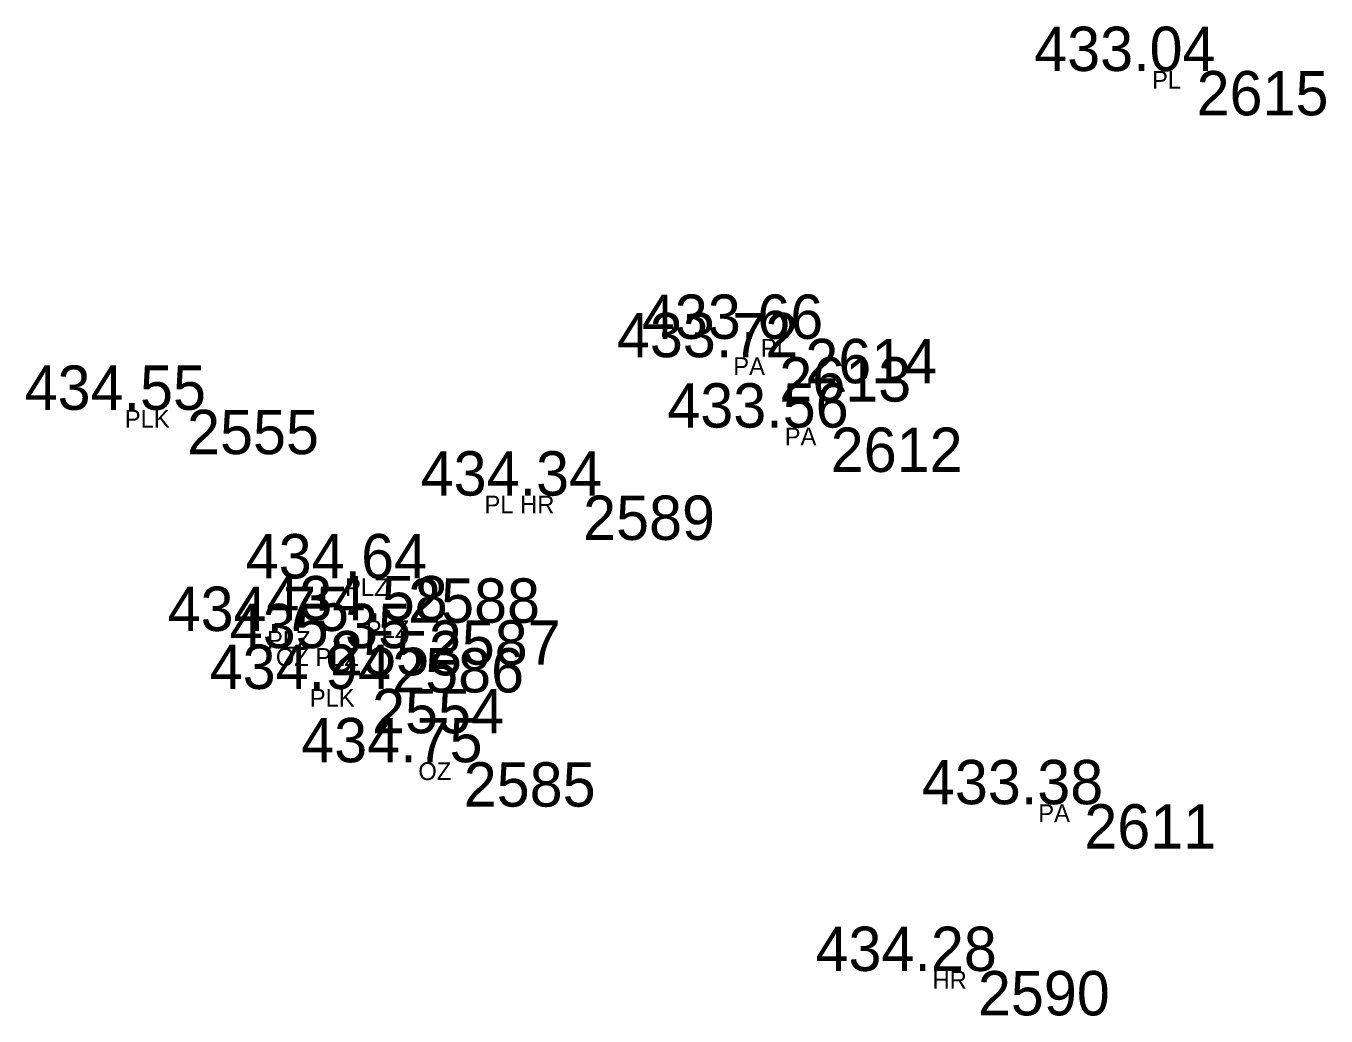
# Model space of a CAD drawing. Extents: x -639390 to -639075, y -1138747 to -1138358.
# Drawn here: x -639365.64 to -639343.64, y -1138399.35 to -1138382.61 of the extents above; entities that cross this region are included whole.
import ezdxf

# ---------------------------------------------------------------- set-up
doc = ezdxf.new("R2010")
doc.units = 0
for name, color, linetype in [('Vrstva 11', 7, 'Continuous'), ('Vrstva 12', 7, 'Continuous'), ('Vrstva 13', 7, 'Continuous'), ('Vrstva 57', 7, 'Continuous')]:
    doc.layers.add(name, color=color, linetype=linetype)

msp = doc.modelspace()

# ---------------------------------------------------------------- linework, layer by layer
at = {"layer": 'Vrstva 11'}
for p, q in [((-639346.11, -1138383.37), (-639346.11, -1138383.37)), ((-639352.73, -1138387.9), (-639352.73, -1138387.9)), ((-639353.17, -1138388.21), (-639353.17, -1138388.21)), ((-639363.19, -1138389.1), (-639363.19, -1138389.1)), ((-639352.3, -1138389.4), (-639352.3, -1138389.4)), ((-639356.49, -1138390.55), (-639356.49, -1138390.55)), ((-639359.45, -1138391.95), (-639359.45, -1138391.95)), ((-639359.1, -1138392.66), (-639359.1, -1138392.66)), ((-639360.77, -1138392.84), (-639360.77, -1138392.84)), ((-639359.72, -1138393.13), (-639359.72, -1138393.13)), ((-639360.06, -1138393.82), (-639360.06, -1138393.82)), ((-639358.51, -1138395.06), (-639358.51, -1138395.06)), ((-639348.01, -1138395.77), (-639348.01, -1138395.77)), ((-639349.81, -1138398.59), (-639349.81, -1138398.59))]:
    msp.add_line(p, q, dxfattribs=at)

# ---------------------------------------------------------------- texts
at = {"layer": 'Vrstva 12'}
for s, p in [('433.04 ', (-639348.579, -1138383.37)), ('433.66 ', (-639355.216, -1138387.9)), ('433.72 ', (-639355.639, -1138388.21)), ('434.55 ', (-639365.66, -1138389.1)), ('433.56 ', (-639354.786, -1138389.4)), ('434.34 ', (-639358.959, -1138390.55)), ('434.64 ', (-639361.919, -1138391.95)), ('434.58 ', (-639361.569, -1138392.66)), ('434.75 ', (-639363.24, -1138392.84)), ('435.35 ', (-639362.19, -1138393.13)), ('434.94 ', (-639362.529, -1138393.82)), ('434.75 ', (-639360.98, -1138395.06)), ('433.38 ', (-639350.479, -1138395.77)), ('434.28 ', (-639352.279, -1138398.59))]:
    msp.add_text(s, height=0.75, dxfattribs=at).set_placement(p)
at = {"layer": 'Vrstva 13'}
for s, p in [(' 2615', (-639346.11, -1138384.12)), (' 2614', (-639352.73, -1138388.65)), (' 2613', (-639353.17, -1138388.96)), (' 2555', (-639363.19, -1138389.85)), (' 2612', (-639352.3, -1138390.15)), (' 2589', (-639356.49, -1138391.3)), (' 2588', (-639359.45, -1138392.7)), (' 2587', (-639359.1, -1138393.41)), (' 2553', (-639360.77, -1138393.59)), (' 2586', (-639359.72, -1138393.88)), (' 2554', (-639360.06, -1138394.57)), (' 2585', (-639358.51, -1138395.81)), (' 2611', (-639348.01, -1138396.52)), (' 2590', (-639349.81, -1138399.34))]:
    msp.add_text(s, height=0.75, dxfattribs=at).set_placement(p)
at = {"layer": 'Vrstva 57'}
for s, p in [('PL', (-639346.585, -1138383.67)), ('PL', (-639353.205, -1138388.2)), ('PA', (-639353.67, -1138388.51)), ('PLK', (-639363.965, -1138389.4)), ('PA', (-639352.8, -1138389.7)), ('PL HR', (-639357.879, -1138390.85)), ('PLZ', (-639360.239, -1138392.25)), ('PLZ', (-639359.889, -1138392.96)), ('PLZ', (-639361.559, -1138393.14)), ('OZ PLZ', (-639361.409, -1138393.43)), ('PLK', (-639360.835, -1138394.12)), ('OZ', (-639358.999, -1138395.36)), ('PA', (-639348.51, -1138396.07)), ('HR', (-639350.299, -1138398.89))]:
    msp.add_text(s, height=0.3, dxfattribs=at).set_placement(p)

doc.saveas('drawing.dxf')
